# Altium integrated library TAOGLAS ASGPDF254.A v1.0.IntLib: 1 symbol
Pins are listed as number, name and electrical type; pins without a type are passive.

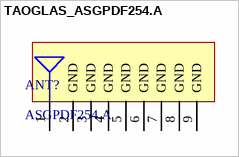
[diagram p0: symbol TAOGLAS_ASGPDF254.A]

## TAOGLAS_ASGPDF254.A
designator ANT?, comment ASGPDF254.A
Stage SMD Active GPS/GLOANASS/BeiDou/Galileo 25*25*4mm Patch; ComponentLibStatus: Created; MFG: Taoglas; Temp_High: +85C; Temp_Low: -40C
footprint TAOGLAS_ASGPDF254.A (Stage SMD Active GPS/GLOANASS/BeiDou/Galileo 25*25*4mm Patch)
pins: 1 RF FEED, 2 GND, 3 GND, 4 GND, 5 GND, 6 GND, 7 GND, 8 GND, 9 GND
